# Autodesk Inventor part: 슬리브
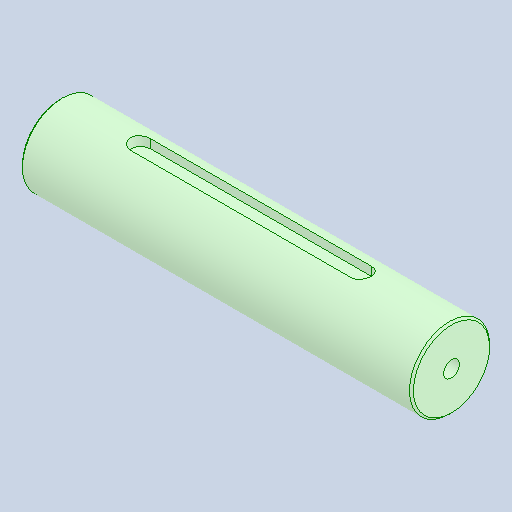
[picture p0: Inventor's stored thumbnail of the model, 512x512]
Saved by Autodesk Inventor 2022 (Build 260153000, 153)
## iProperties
Created: 2024-07
Part Number: 슬리브
Material: 강철, 탄소
Document SubType Name: Modeling
Designer: PC-01
Density: 7.85 g/cm^3
Appearance: 기본값
Author: jhkim
Sending System: Autodesk Inventor 2025
Preprocessor: ST-DEVELOPER v20
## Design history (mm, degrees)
feature "솔리드1"
node "솔리드2"
